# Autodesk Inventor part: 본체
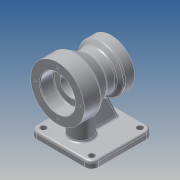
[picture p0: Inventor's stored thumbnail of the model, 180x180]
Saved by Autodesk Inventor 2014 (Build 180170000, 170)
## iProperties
Created: 2019-01
Part Number: 본체
Material: 알루미늄 6061
Document SubType Name: Modeling
Designer: kb542-15
Density: 2.71 g/cm^3
Appearance: 알루미늄 - 평지
Author: kb542-15
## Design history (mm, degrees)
sketch "스케치1"
  geometry: L1 (0, 0)-(92, 0); L2 (92, 0)-(92, 92); L3 (92, 92)-(0, 92); L4 (0, 92)-(0, 0)
  constraints: 8 end point, 2 parallel, 1 horizontal, 1 perpendicular
  dimensions: "d0" = 92 distance between parallel lines of L2 L4; "d1" = 92 distance between parallel lines of L1 L3
extrude "돌출1" new body sketch "스케치1" distance "d2" = 10; taper "d3" = 0 deg
fillet "모깎기1" dims "d4" = 10
sketch "스케치3"
  geometry: L1 (82, 92)-(10, 92) reference; L2 (0, 82)-(0, 10) reference; L3 (10, 0)-(82, 0) reference; L4 (92, 10)-(92, 82) reference; C1 r 4.5 at (10, 82); C2 r 4.5 at (82, 82); C3 r 4.5 at (82, 10); C4 r 4.5 at (10, 10); A1 r 10 centre (10, 82) between (10, 92) and (0, 82) reference; A2 r 10 centre (82, 82) between (92, 82) and (82, 92) reference; A3 r 10 centre (82, 10) between (82, 0) and (92, 10) reference; A4 r 10 centre (10, 10) between (0, 10) and (10, 0) reference; 1 further point
  constraints: 4 centre point, 4 coincident, 3 equal radius
  dimensions: "d5" = 9 diameter of C1
extrude "돌출2" cut sketch "스케치3" distance "d6" = 10; taper "d7" = 0 deg
node "작업 평면1"
sketch "스케치4"
  geometry: L1 (-5, 80)-(75, 80); L2 (10, 0)-(82, 0) reference; L3 (0, 10)-(0, 0) reference; L4 (-5, 120)-(20, 120); L5 (20, 120)-(40.785, 108); L6 (40.785, 108)-(54.126, 108); L7 (54.126, 108)-(60, 115); L8 (60, 115)-(75, 115); L9 (-5, 120)-(-5, 106); L10 (-5, 106)-(15, 106); L11 (15, 106)-(15, 96); L12 (15, 96)-(58, 96); L13 (58, 96)-(58, 100); L14 (58, 100)-(75, 100); L15 (75, 100)-(75, 115)
  constraints: 26 end point, 7 parallel, 3 perpendicular, 2 vertical alignment, 1 horizontal
  dimensions: "d8" = 80 distance between parallel lines of L2 L1; "d10" = 5 distance from line of L3 L1.start; "d11" = 80 distance of L1.start L1.end; "d12" = 80 diameter of L4 L1; "d13" = 56 diameter of L6 L1; "d14" = 70 diameter of L8 L1; "d16" = 25 distance of L4.end L4.start; "d17" = 15 distance of L8.end L7.end; "d18" = 30 deg angle of L6 L5; "d19" = 50 deg angle of L6 L7; "d20" = 52 diameter of L10 L1; "d21" = 20 distance between parallel lines of L9 L11; "d22" = 32 diameter of L12 L1; "d23" = 40 diameter of L14 L1; "d24" = 17 distance between parallel lines of L15 L13
revolve "회전1" sketch "스케치4" stored, may be unused: angle "d25" = 90 deg
sketch "스케치5"
  geometry: L1 (0, 82)-(0, 10) reference; L2 (82, 92)-(10, 92) reference; L3 (92, 10)-(92, 82) reference; L4 (10, 0)-(82, 0) reference; C1 r 4.5 at (82, 10) reference; C2 r 4.5 at (10, 82) reference; C3 r 4.5 at (82, 82) reference; C4 r 4.5 at (10, 10) reference; C5 r 16 at (46, 30); A1 r 10 centre (10, 10) between (0, 10) and (10, 0) reference; A2 r 10 centre (10, 82) between (10, 92) and (0, 82) reference; A3 r 10 centre (82, 82) between (92, 82) and (82, 92) reference; A4 r 10 centre (82, 10) between (82, 0) and (92, 10) reference; 1 further point
  constraints: 1 centre point
  dimensions: "d26" = 30 distance from line of C5.centre L4; "d27" = 46 distance from line of C5.centre L1; "d28" = 16 radius of C5
extrude "돌출3" join sketch "스케치5" stored distance "d29" = 10; taper "d30" = 0 deg
node "작업 평면2"
sketch "스케치6"
  geometry: L1 (66.803, 42.104)-(82, 9.514); L2 (92, 0)-(92, 10) reference; 1 further point
  constraints: 2 end point
  dimensions: "d31" = 10 distance from line of L2 L1.end; "d32" = 25 deg angle of L2 L1
feature "리브1" sketch "스케치6" dims "d33" = 1, "d34" = 10, "d35" = 0, "d36" = 0, "d37" = 1, "d38" = 1
sketch "스케치7" dims "d39" = 66
  geometry: C1 r 26 at (0, 0) reference; C2 r 40 at (0, 0) reference; 3 further points
  constraints: 2 vertical alignment, 1 coincident, 2 other
hole "구멍1" sketch "스케치7" at (0, 33) diameter "d40" = 3.242; stored, may be unused: countersink angle "d44" = 90 deg, drill point angle "d46" = 118 deg; dims "d41" = 9, "d42" = 4, "d43" = 2, "d45" = 11
sketch "스케치8" dims "d50" = 55
  geometry: C1 r 35 at (0, 0) reference; 3 further points
  constraints: 2 vertical alignment, 1 coincident, 2 other
hole "구멍2" sketch "스케치8" at (0, -27.5) diameter "d51" = 3.242; stored, may be unused: countersink angle "d55" = 90 deg, drill point angle "d57" = 118 deg; dims "d52" = 9, "d53" = 4, "d54" = 2, "d56" = 11
fillet "모깎기2" dims "d61" = 3
fillet "모깎기3" dims "d62" = 3
fillet "모깎기4" dims "d63" = 1, "d64" = 0.6
chamfer "모따기1" distance "d65" = 1; stored, may be unused: second distance "d66" = 2, angle "d67" = 45 deg
node "솔리드1"
pattern_circular "원형 패턴1" dims angle "d48" = 360 deg
pattern_circular "원형 패턴2" dims angle "d59" = 360 deg
node "투영된 루프1"
